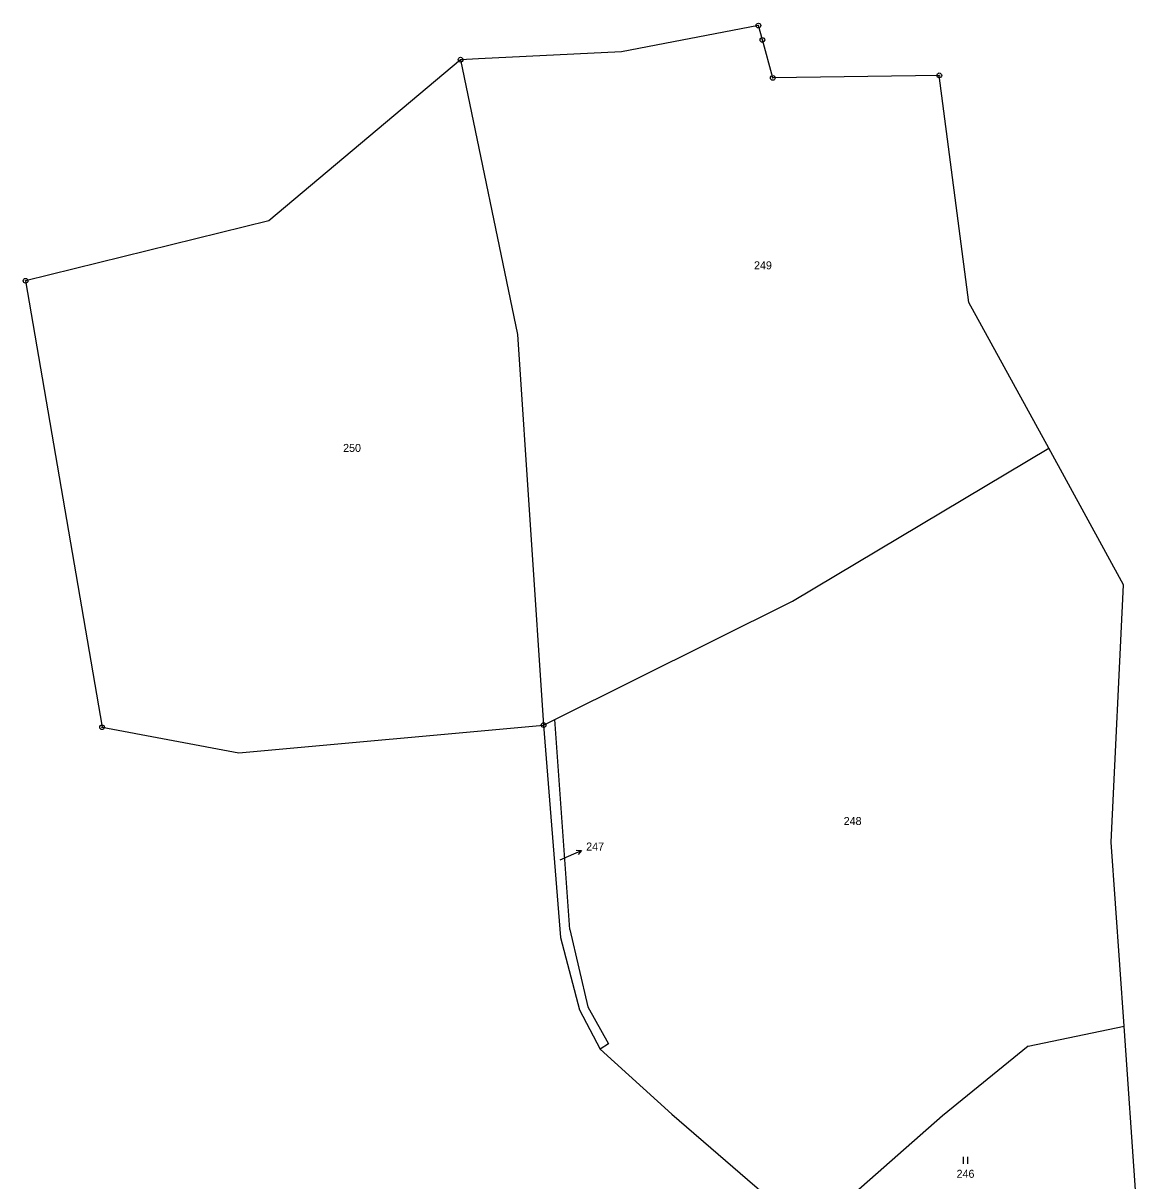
# Model space of a CAD drawing. Extents: x -760642 to -757221, y -1092371 to -1088855.
# Drawn here: x -759002.3 to -758765.9, y -1089100.6 to -1088854.7 of the extents above; entities that cross this region are included whole.
import ezdxf

# ---------------------------------------------------------------- set-up
doc = ezdxf.new("R2010")
doc.units = 0
for name, color, linetype in [('Vrstva 1', 7, 'Continuous'), ('Vrstva 13', 7, 'Continuous'), ('Vrstva 16', 7, 'Continuous'), ('Vrstva 18', 7, 'Continuous'), ('Vrstva 24', 7, 'Continuous'), ('Vrstva 25', 7, 'Continuous')]:
    doc.layers.add(name, color=color, linetype=linetype)

msp = doc.modelspace()

# ---------------------------------------------------------------- linework, layer by layer
at = {"layer": 'Vrstva 1'}
for p, q in [((-758909.35, -1088862.44), (-758897.27, -1088920.85)), ((-758897.27, -1088920.85), (-758891.7, -1089003.82)), ((-758838.82, -1088977.47), (-758784.37, -1088945.01)), ((-758889.32, -1089002.63), (-758838.82, -1088977.47)), ((-758891.7, -1089003.82), (-758889.32, -1089002.63)), ((-758886.11, -1089047.26), (-758889.32, -1089002.63)), ((-758886.11, -1089047.26), (-758882.29, -1089063.69)), ((-758882.29, -1089063.69), (-758877.9, -1089071.51)), ((-758788.74, -1089072.03), (-758768.37, -1089067.76)), ((-758877.9, -1089071.51), (-758879.67, -1089072.7)), ((-758788.74, -1089072.03), (-758806.96, -1089086.83)), ((-758806.96, -1089086.83), (-758835.2, -1089111.71))]:
    msp.add_line(p, q, dxfattribs=at)
at = {"layer": 'Vrstva 13'}
for p, q in [((-758846.05, -1088855.18), (-758875.15, -1088860.76)), ((-758845.21, -1088858.25), (-758846.05, -1088855.18)), ((-758843, -1088866.32), (-758845.21, -1088858.25)), ((-758875.15, -1088860.76), (-758905.51, -1088862.25)), ((-758909.35, -1088862.44), (-758950.11, -1088896.65)), ((-758905.51, -1088862.25), (-758909.35, -1088862.44)), ((-758807.62, -1088865.77), (-758843, -1088866.32)), ((-758805.65, -1088880.97), (-758807.62, -1088865.77)), ((-758801.38, -1088914.02), (-758805.65, -1088880.97)), ((-758950.11, -1088896.65), (-759001.79, -1088909.41)), ((-759001.79, -1088909.41), (-758985.53, -1089004.28)), ((-758784.37, -1088945.01), (-758801.38, -1088914.02)), ((-758768.47, -1088973.99), (-758784.37, -1088945.01)), ((-758771.1, -1089028.7), (-758768.47, -1088973.99)), ((-758985.53, -1089004.28), (-758956.43, -1089009.74)), ((-758956.43, -1089009.74), (-758891.7, -1089003.82)), ((-758891.7, -1089003.82), (-758888.09, -1089048.97)), ((-758768.37, -1089067.76), (-758771.1, -1089028.7)), ((-758888.09, -1089048.97), (-758884.09, -1089064.31)), ((-758884.09, -1089064.31), (-758879.67, -1089072.7)), ((-758765.86, -1089103.63), (-758768.37, -1089067.76)), ((-758879.67, -1089072.7), (-758864.44, -1089086.48)), ((-758864.44, -1089086.48), (-758835.2, -1089111.71))]:
    msp.add_line(p, q, dxfattribs=at)
at = {"layer": 'Vrstva 16'}
for p, q in [((-758886.4, -1089031.67), (-758883.649, -1089030.474)), ((-758888.16, -1089032.43), (-758886.4, -1089031.67))]:
    msp.add_line(p, q, dxfattribs=at)
msp.add_lwpolyline([(-758884.765, -1089030.414), (-758883.649, -1089030.474), (-758884.366, -1089031.331)], dxfattribs=at)
at = {"layer": 'Vrstva 24'}
for centre, radius in [((-758846.05, -1088855.18), 0.5), ((-758846.05, -1088855.18), 0.0327), ((-758845.21, -1088858.25), 0.5), ((-758845.21, -1088858.25), 0.0327), ((-758909.35, -1088862.44), 0.5), ((-758909.35, -1088862.44), 0.0327), ((-758843, -1088866.32), 0.5), ((-758843, -1088866.32), 0.5), ((-758843, -1088866.32), 0.0327), ((-758843, -1088866.32), 0.0327), ((-758807.62, -1088865.77), 0.5), ((-758807.62, -1088865.77), 0.5), ((-758807.62, -1088865.77), 0.0327), ((-758807.62, -1088865.77), 0.0327), ((-759001.79, -1088909.41), 0.5), ((-759001.79, -1088909.41), 0.0327), ((-758985.53, -1089004.28), 0.5), ((-758985.53, -1089004.28), 0.0327), ((-758891.7, -1089003.82), 0.5), ((-758891.7, -1089003.82), 0.0327)]:
    msp.add_circle(centre, radius, dxfattribs=at)
at = {"layer": 'Vrstva 25'}
for p, q in [((-758802.577, -1089095.565), (-758802.577, -1089097.065)), ((-758801.555, -1089097.065), (-758801.555, -1089095.565))]:
    msp.add_line(p, q, dxfattribs=at)

# ---------------------------------------------------------------- texts
at = {"layer": 'Vrstva 16'}
msp.add_text('247', height=1.7, dxfattribs=at).set_placement((-758882.65, -1089030.47))
at = {"layer": 'Vrstva 18'}
for s, height, p in [('249', 1.7, (-758846.99, -1088906.98)), ('250', 1.7, (-758934.3, -1088945.78)), ('248', 1.7, (-758827.94, -1089025.05)), ('247', 0.1, (-758888.242, -1089032.43)), ('246', 1.7, (-758803.95, -1089100))]:
    msp.add_text(s, height=height, dxfattribs=at).set_placement(p)

doc.saveas('drawing.dxf')
